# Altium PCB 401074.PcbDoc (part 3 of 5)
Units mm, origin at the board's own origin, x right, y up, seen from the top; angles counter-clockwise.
Board outline 70.15 x 35.15 mm, 6 copper layers (Top Layer, Mid-Layer1, Mid-Layer2, Mid-Layer3, Mid-Layer4, Bottom Layer), stack 1.549 mm thick; 239 components, 182 nets, 1034 pads, 1263 vias.
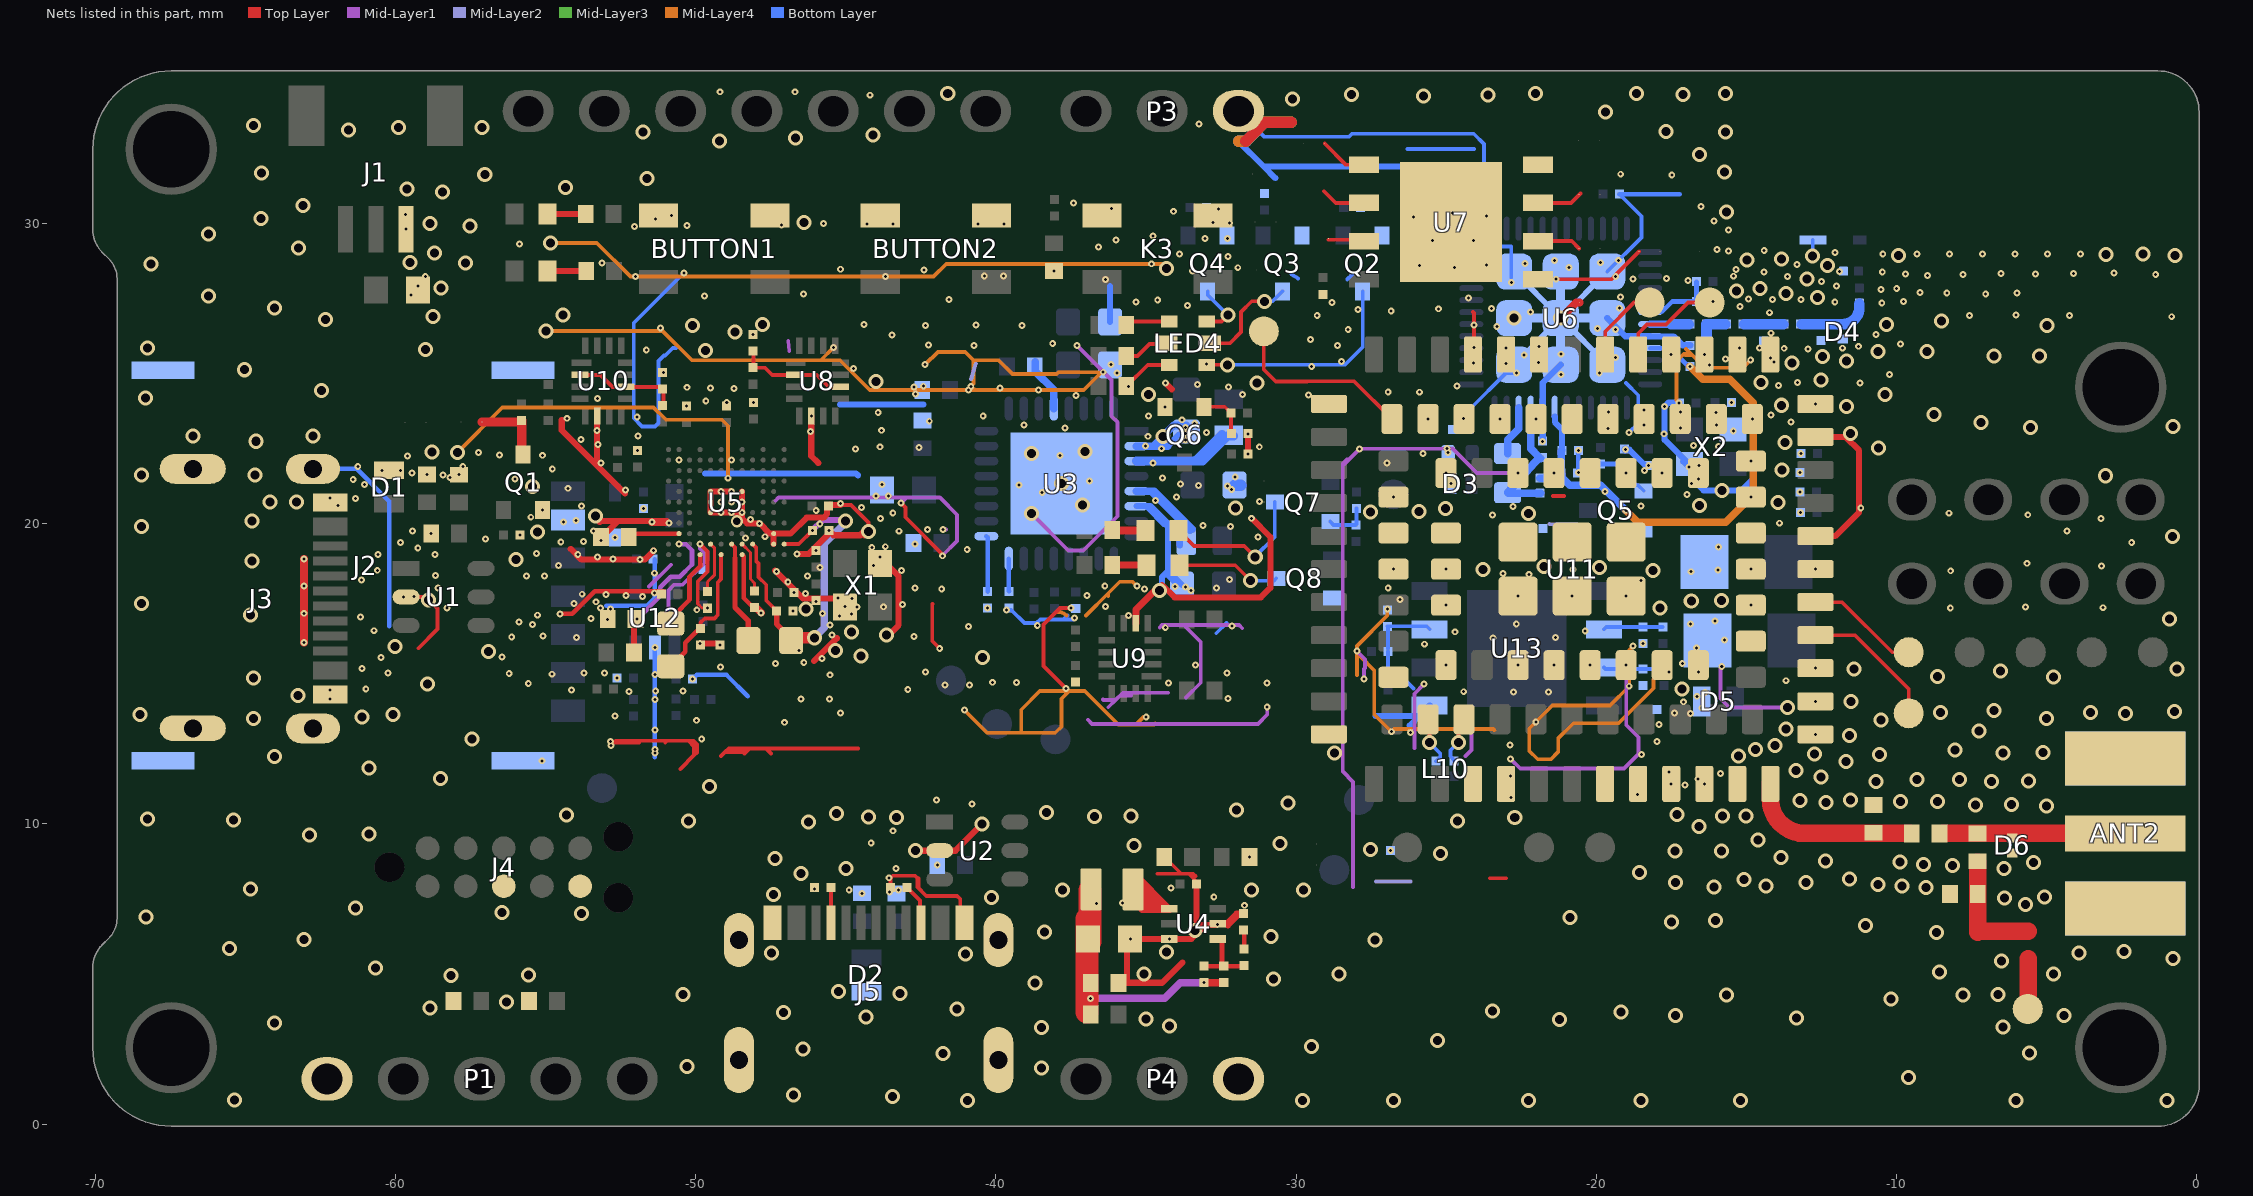
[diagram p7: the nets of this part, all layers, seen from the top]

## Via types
v1: diameter 0.23, hole 0.1, Top Layer to Mid-Layer1, tented both sides, 505 vias
v2: diameter 0.5, hole 0.3, Top Layer to Bottom Layer, tented both sides, 430 vias
v3: diameter 0.23, hole 0.1, Mid-Layer4 to Bottom Layer, tented both sides, 176 vias
v4: diameter 0.23/0.23 (per signal layer), hole 0.1, Mid-Layer4 to Bottom Layer, tented both sides, 144 vias
v5: diameter 0.5, hole 0.3, Top Layer to Bottom Layer, tented top, 7 vias
v6: diameter 0.4, hole 0.25, Top Layer to Bottom Layer, tented both sides, 1 vias

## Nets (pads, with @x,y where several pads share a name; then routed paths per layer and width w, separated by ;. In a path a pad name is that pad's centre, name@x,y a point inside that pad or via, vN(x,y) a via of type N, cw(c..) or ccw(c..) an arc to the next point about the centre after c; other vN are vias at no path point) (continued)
GND: ANT1.2 ANT2.2 BUTTON1.3 BUTTON1.4 BUTTON2.3 BUTTON2.4 C1.1 C2.1 C3.1 C4.1 C5.1 C6.1 C7.1 C8.1 C9.1 C10.1 C11.1 C12.1 C13.1 C14.1 C15.1 C16.1 C17.1 C18.1 C20.1 C21.1 C22.1 C23.1 C24.1 C25.1 C26.1 C27.1 C28.1 C29.1 C30.1 C31.1 C32.1 C33.1 C34.1 C35.1 C36.1 C37.1 C38.1 C39.2 C40.1 C41.1 C42.1 C43.1 C44.1 C45.1 C47.1 C48.1 C49.1 C50.1 C51.1 C52.1 C53.1 C54.1 C55.1 C56.2 C57.1 C58.1 C59.1 C60.1 C61.1 C62.1 C63.1 C64.1 C65.1 C67.1 C68.2 C69.1 C70.1 C71.1 C72.1 C73.1 C74.1 C75.1 C76.1 C77.1 C78.1 C79.2 C80.2 D1.A D2.A D3.A D4.A D5.A D6.A D7.K J1.1 J2.0@-55.742,12.097 J2.0@-55.742,25.097 J2.0@-67.742,12.097 J2.0@-67.742,25.097 J2.5 J3.0 J3.A1 J3.A12 J3.B1 J3.B12 J4.3 J4.5 J5.0 J5.A1 J5.A12 J5.B1 J5.B12 K3.3 K3.4 P1.1 P3.3 P4.3 pad.10 Q1.S Q2.S Q3.S Q4.S Q5.E Q6.E Q7.S Q8.S R1.1 R4.1 R5.1 R10.1 R13.1 R20.1 R22.2 R27.2 R28.2 R29.2 R31.2 R32.2 R33.1 R34.1 R45.2 R46.2 R53.2 R54.2 SB1.1 SB5.1 SB16.1 U1.2 U2.2 U3.0 U3.2 U3.6 U4.2 U4.6 U5.A5 U5.B2 U5.B9 U5.C2 U5.D12 U5.E5 U5.E6 U5.E7 U5.E8 U5.F5 U5.F6 U5.F7 U5.F8 U5.G5 U5.G6 U5.G7 U5.G8 U5.K6 U5.K11 U6.32 U6.44 U6.49 U7.4 U7.9 U8.6 U9.6 U10.6 U11.1 U11.2 U11.3 U11.4 U11.8 U11.9 U11.10 U11.26 U11.27 U11.30 U11.31 U11.32 U11.33 U11.34 U11.36 U11.37 U11.40 U11.41 U11.44 U11.45 U11.46 U11.47 U11.48 U11.49 U11.50 U11.51 U11.52 U11.53 U11.54 U11.55 U11.56 U11.68 U11.69 U11.70 U11.71 U11.72 U11.73 U11.74 U11.75 U11.76 U11.77 U11.78 U11.80 U11.81 U11.83 U11.84 U11.85 U11.86 U11.87 U11.88 U11.89 U11.90 U11.91 U11.92 U11.93 U11.94 U11.95 U11.96 U11.97 U11.98 U11.99 U11.102 U11.106 U11.107 U11.108 U11.109 U12.2 U13.1 X1.2 X1.4 X2.2 X2.4 | length 393.3
  Top Layer w0.102: -49.929,18.072 -49.929,17.324 -49.79,17.184 v1(-49.61,17.184)
  Top Layer w0.127: v1(-59.731,17.554) -59.553,17.554 -59.552,17.556 -58.991,17.556 -58.599,17.164 -58.599,16.481 -59.234,15.846 ; v1(-52.82,12.604) -52.729,12.696 ; -51.88,12.696 -52.729,12.696 ; -51.013,12.696 -50.947,12.762 ; -50.509,11.827 -50.052,12.284 ; -49.929,18.072 -49.609,18.392 -49.609,19.071 v1(-49.85,19.312) ; -49.15,12.251 -49.017,12.385 ; -48.369,12.34 -48.324,12.385 ; -47.491,12.34 -47.659,12.508 ; C29.1@-45.572,20.575 -45.524,20.624 C29.1@-45.505,20.624 ; -45.178,20.611 -44.82,20.611 -44.244,20.035 v2(-44.244,19.729) ; -44.597,12.508 -47.659,12.508 ; R34.1@-43.507,7.875 -43.507,8.192 -43.433,8.267 -42.689,8.267 -42.615,8.192 -42.615,7.891 -42.321,7.597 -41.296,7.597 -41.188,7.489 ; v1(-43.155,20.679) -43.014,20.538 -43.014,20.207 v1@-41.758,18.951 ; -42.574,7.883 -42.574,8.184 ; v1@-42.301,19.794 v1(-42.273,19.794) ; -42.108,17.321 -42.117,17.312 -42.117,16.082 v1(-41.87,15.835) ; J5.B1@-41.188,6.704 -41.188,7.488 ; v1(-37.663,14.504) -38.418,15.259 -38.418,16.635 -37.868,17.184 v1(-37.495,17.184) ; -34.626,8.333 -33.825,8.333 ; C17.1@-34.392,8.899 -33.825,8.333 ; -33.348,8.254 -33.426,8.333 -33.572,8.333 ; R10.1@-33.341,8.102 -33.572,8.333 ; U11.95@-28.907,23.979 U11.95@-28.849,23.979 ; -24.107,27.039 -24.079,27.012 v1(-24.079,26.613) v1(-24.079,25.86) ; -23.549,8.182 -23.007,8.182 ; -21.442,20.912 -21.074,20.912 ; -52.729,12.696 -52.663,12.762 -50.947,12.762 ; -50.947,12.762 -50.242,12.762 ; -50.242,12.762 -50.074,12.762 -49.958,12.647 -49.958,12.377 -50.052,12.284 ; -50.242,12.762 -50.052,12.572 -50.052,12.284 ; -49.017,12.385 -48.894,12.508 -48.201,12.508 ; -49.017,12.385 -48.324,12.385 ; -48.324,12.385 -48.201,12.508 ; -48.201,12.508 -47.659,12.508 ; -33.825,8.333 -33.572,8.333
  Top Layer w0.152: v1(-54.511,16.99) -54.11,16.99 -53.358,17.742 C31.1@-51.067,17.742 ; U5.A5@-48.45,18.962 -48.398,18.91 -48.398,17.52 -48.082,17.204 C35.1@-48.045,17.204 ; C35.1@-48.045,17.134 C35.1@-48.014,17.134
  Top Layer w0.203: -54.457,23.446 -54.457,23.105 -53.279,21.927 ; -54.16,19.152 -53.807,18.799 v1(-51.85,18.799) -51.694,18.799 v1(-51.4,19.092) ; U10.6@-53.279,23.581 v1(-53.279,23.104) -53.279,21.927 ; v2@-53.194,20.053 -53.165,20.082 -52.587,20.082 ; v1(-53.155,19.429) C34.1@-53.155,19.553 -53.116,19.553 -52.587,20.082 ; -52.347,20.995 -53.279,21.927 ; U5.D12@-50.9,20.012 -51.462,20.012 v1@-51.531,20.082 ; v1(-50.889,20.016) -50.956,20.082 v1@-51.531,20.082 ; v1(-49.85,16.004) -49.246,16.004 v1(-49.188,15.946) C25.1@-49.188,15.942 ; v1(-48.8,21.062) U5.G8@-49.5,21.062 U5.F8@-49.5,20.712 U5.E8@-49.5,20.362 v1(-48.8,20.362) v1(-48.45,20.362) ; U5.G5@-48.45,21.062 v1(-48.45,20.712) v1(-48.45,20.362) ; U5.B2@-47.4,19.312 U5.C2@-47.4,19.662 ; v1@-47.355,18.438 v1(-47.312,18.395) -46.424,17.508 X1.2@-45.098,17.508 ; v1@-46.611,18.989 -46.226,18.989 C27.1@-45.562,19.653 ; v1(-46.147,23.582) -46.147,22.248 -45.915,22.016 ; -46.052,15.423 -45.297,16.178 ; v1(-45.987,17.404) C79.2@-45.987,17.429 ; C29.1@-45.572,20.575 -45.621,20.527 -45.621,20.316 -45.74,20.197 -46.306,20.197 -46.84,19.662 U5.C2@-47.4,19.662 ; v1(-45.562,19.768) -45.404,19.61 -44.519,19.61 v2@-44.449,19.679 ; C29.1@-45.524,20.624 -45.524,20.611 -45.178,20.611 ; X1.2@-45.11,17.312 v1(-45.03,17.231) ; v2@-44.432,19.662 v2@-44.379,19.61 ; v1(-43.867,18.877) -43.238,18.248 -43.238,16.616 v2@-43.606,16.249 ; v2(-42.672,9.102) U2.2@-41.87,9.102 -41.351,9.102 v2(-40.459,9.994) ; C21.1@-35.917,4.703 -35.616,4.703 ; C20.1@-35.629,5.929 -35.629,4.716 -35.616,4.703 ; C20.1@-35.527,6.167 v1(-35.522,6.161) v1(-34.218,6.161) -33.487,6.161 -33.174,6.474 -33.174,6.622 ; v2@-34.461,17.95 -34.048,17.538 -31.179,17.538 -30.859,17.858 -30.859,19.55 v1(-31.483,20.174) ; v1(-34.356,24.683) -34.143,24.469 ; -33.783,5.384 -34.464,4.703 -35.616,4.703 ; R10.1@-33.314,7.955 -33.314,6.762 -33.174,6.622 ; -32.273,6.618 -31.923,6.968 ; R13.1@-31.75,7.011 -31.98,7.011 -32.33,6.661 U4.2@-32.618,6.661 -32.657,6.622 -33.174,6.622 ; v1(-31.608,22.307) v1(-31.608,22.989) R46.2@-31.6,22.996 ; U11.41@-12.707,19.579 -12.047,19.579 -11.252,20.374 -11.252,22.433 -11.698,22.879 U11.44@-12.707,22.879 ; -52.587,20.082 v1@-51.531,20.082 ; v1(-48.45,20.362) -48.45,20.166 -48.286,20.001 v1(-47.869,20.001) -47.53,19.662 U5.C2@-47.4,19.662
  Top Layer w0.229: U9.6@-35.338,16.677 -35.338,17.133 -34.697,17.773 v2(-34.544,17.773)
  Top Layer w0.254: v1(-63.043,16.03) v1(-63.043,17.01) v1(-63.043,17.917) v1(-63.043,18.824) ; C35.1@-48.045,17.204 -47.994,17.204 v1@-47.816,17.026 ; v5(-21.187,26.837) -20.665,27.36 SB1.1@-20.555,27.36
  Top Layer w0.381: -31.672,32.735 -31.037,33.369 -30.156,33.369
  Mid-Layer1 w0.127: -51.551,17.898 -50.825,18.624 ; -50.903,17.129 -50.903,17.773 -50.717,17.959 -50.435,17.959 -49.709,18.686 ; v1@-49.86,19.312 v1@-49.85,19.302 ; v1(-49.85,19.312) v1@-49.85,19.302 ; -47.346,20.754 -47.234,20.867 -42.968,20.867 ; -46.914,26.08 -46.883,25.735 ; v1(-43.155,20.679) -42.968,20.867 ; v1(-41.783,18.925) -41.29,19.419 -41.29,20.29 -41.866,20.867 -42.968,20.867 ; v1(-41.758,19.798) v1@-41.651,19.798 ; v5(-38.818,20.328) -37.59,19.1 -37.089,19.1 -35.947,20.242 -35.947,23.375 -36.146,23.574 -36.146,24.778 v1(-37.3,25.932) ; -36.929,13.462 -36.793,13.326 -31.272,13.326 -30.962,13.636 v1(-30.962,13.886) ; -36.427,14.137 -36.412,14.122 -36.015,14.122 ; -36.255,13.882 -36.015,14.122 ; -35.835,14.276 -35.496,14.276 ; -34.542,16.539 -34.464,16.618 -31.903,16.618 -31.795,16.509 ; -34.271,14.362 -35.775,14.362 -36.015,14.122 ; -33.679,16.559 -33.179,16.058 -33.179,14.694 -33.666,14.207 ; -28.265,22.1 -28.444,21.921 ; -28.101,7.89 -28.101,11.393 -28.444,11.736 -28.444,21.921 ; v1(-27.979,15.748) -27.709,15.478 -27.709,15.179 -27.739,15.15 v1(-27.739,14.823) ; -26.061,12.524 -26.061,14.328 v1(-25.739,14.65) ; -24.359,12.251 -24.155,12.455 -24.155,12.999 -24.206,13.05 ; v1(-22.858,12.161) -22.533,11.836 -19.075,11.836 -18.593,12.318 -18.593,12.879 -19.007,13.293 v1(-19.007,15.279) ; v1(-22.607,21.679) -23.973,21.679 -24.793,22.499 v1(-24.972,22.499) -24.979,22.492 -27.882,22.492 v1(-27.889,22.485) -28.238,22.136 -28.302,22.136 -28.444,21.994 -28.444,21.921 ; v1(-15.825,15.242) -15.867,15.199 -15.867,14.168 -15.572,13.873 v2(-13.637,13.873) ; v1@-49.85,19.302 -49.85,19.166 -49.709,19.025 -49.709,18.686 ; v1@-49.85,19.302 -49.597,19.049 -49.597,18.798 -49.709,18.686
  Mid-Layer3 w0.381: -31.672,32.735 -31.037,33.369 -30.156,33.369
  Mid-Layer4 w0.127: v2(-57.935,22.37) -56.441,23.864 -51.398,23.864 -50.988,23.454 -49.119,23.454 -48.92,23.255 v3(-48.92,21.508) ; v2(-54.987,26.414) -51.102,26.414 -50.125,25.437 -45.831,25.437 ; v2(-54.827,29.347) -53.291,29.347 -52.17,28.225 v3(-52.003,28.225) v3(-43.673,28.225) -42.077,28.225 -41.655,28.646 -34.463,28.646 v2(-34.31,28.493) ; v2@-48.681,26.336 v2(-48.681,26.378) ; v4(-45.408,25.86) -45.831,25.437 ; v4(-42.355,25.29) -41.932,25.713 -41.019,25.713 -40.74,25.435 ; v3(-41.051,13.787) -40.292,13.028 -39.157,13.028 ; -37.931,17.053 cw(c-37.931,16.652) -37.648,16.935 ; -36.995,16.938 -36.259,17.674 ; v4@-36.442,25.074 v4@-36.478,25.038 ; v4(-36.424,25.038) v4@-36.478,25.038 ; -36.259,17.575 -36.259,17.674 ; v3(-35.306,17.916) -35.448,18.058 -35.875,18.058 -36.259,17.674 ; v3(-34.993,13.552) -35.079,13.552 -35.33,13.301 ; -34.692,13.347 -34.738,13.301 -35.33,13.301 ; -27.975,14.943 -27.975,15.921 -26.963,16.934 v4(-26.963,17.151) ; -27.859,15.565 -27.399,15.106 -27.399,13.642 v3(-26.823,13.065) -26.737,13.151 -23.43,13.151 -23.39,13.111 ; v4(-18.775,15.92) -18.905,15.789 v4(-18.905,14.58) -19.549,13.937 -21.471,13.937 v4(-22.019,13.389) -22.235,13.173 -22.235,12.427 -21.955,12.147 -21.511,12.147 -21.273,12.385 -21.273,12.839 -20.765,13.347 -19.26,13.347 -18.096,14.511 -18.096,14.8 -17.899,14.997 ; v3(-17.251,24.021) -17.335,24.105 -17.335,25.398 -17.076,25.656 -16.858,25.656 ; -17.038,25.605 -16.82,25.605 ; -17.012,25.811 -16.858,25.656 ; -16.52,25.337 v4@-16.302,25.337 ; v4(-16.231,25.284) -16.485,25.284 ; v4(-14.859,25.445) -15.116,25.188 -16.389,25.188 -16.485,25.284 ; -45.831,25.437 -45.196,25.437 -44.203,24.444 -40.697,24.444 ; -40.74,25.435 -39.908,25.435 -39.448,24.975 -37.982,24.975 -37.918,25.038 v4@-36.478,25.038 ; -40.74,25.435 -40.74,24.652 v4(-40.836,24.556) -40.809,24.556 -40.697,24.444 ; -40.697,24.444 -37.073,24.444 v4@-36.478,25.038 ; -39.157,13.028 -38.022,13.028 -37.818,13.232 -37.818,14.161 -37.562,14.417 ; -39.157,13.028 -39.157,13.798 -38.538,14.417 -37.562,14.417 ; -37.562,14.417 -37.039,14.417 -35.922,13.301 -35.33,13.301 ; -16.858,25.656 -16.485,25.284
  Mid-Layer4 w0.381: -31.92,32.735 -31.672,32.735 -31.037,33.369 -30.156,33.369
  Mid-Layer2 w0.127: -40.83,24.801 -40.665,25.318 ; -27.342,8.073 -26.192,8.073 ; -21.561,19.984 -21.55,19.974 -20.65,19.974
  Mid-Layer2 w0.152: -17.944,21.304 -17.608,21.304
  Bottom Layer w0.127: -50.658,25.849 -50.759,25.849 -51.012,25.596 -51.053,25.596 -51.235,25.415 -51.235,23.353 -51.354,23.233 -51.781,23.233 -52.061,23.513 -52.061,26.673 v3(-50.394,28.341) ; v3(-39.649,17.12) -39.487,17.12 -39.05,16.682 -38.647,16.682 -38.521,16.808 -37.432,16.808 v3(-37.385,16.854) ; -37.745,16.809 -37.619,16.935 ; -32.661,16.343 -32.322,16.682 ; P3.3@-31.92,33.735 -31.287,33.102 -31.068,32.883 -28.231,32.883 -28.134,32.98 -24.085,32.98 -23.745,32.64 -23.745,29.416 -23.556,29.227 ; -30.161,28.301 -29.938,28.164 ; Q7.S@-28.862,20.062 -28.751,19.952 R54.2@-28.012,19.952 -27.985,19.979 R53.2@-27.985,20.502 ; -28.3,28.129 -28.132,28.297 ; -26.417,14.905 -26.417,14.832 -26.088,14.502 ; -26.299,32.475 -24.074,32.475 ; -24.458,23.805 -24.22,23.805 -23.013,25.011 v4(-22.657,25.011) ; -23.369,29.04 -23.556,29.227 ; U6.49@-22.835,28.185 -22.835,29.227 -23.556,29.227 ; U6.49@-19.637,28.387 -18.502,29.522 -18.502,30.235 C41.1@-19.236,30.969 ; -19.013,24.678 -18.608,24.273 -18.608,23.33 v4(-18.908,23.029) ; v2@-12.802,28.949 v2@-12.802,28.92 ; v2(-12.799,28.917) v2@-12.802,28.92 ; ANT1.2@-12.791,29.444 -12.791,28.931 v2@-12.802,28.92
  Bottom Layer w0.152: J3.0@-62.747,21.82 -61.286,21.82 -60.199,20.732 -60.199,16.575 ; -52.975,17.264 -51.615,17.264 -51.368,17.511 C71.1@-51.368,18.805 ; -51.368,12.216 -51.359,12.225 v3(-51.359,14.97) v3(-51.359,15.867) ; v3(-50.1,14.823) -49.967,14.956 -48.971,14.956 -48.26,14.245 ; C51.1@-20.625,21.676 v3(-20.6,21.701) -20.6,21.702 v3(-20.6,22.439) ; C41.1@-19.236,30.969 -17.217,30.969 ; R45.2@-19.055,22.486 R45.2@-19.034,22.464
  Bottom Layer w0.203: -49.68,21.662 -44.654,21.662 -44.597,21.606 ; -45.191,23.961 -42.418,23.961 ; C14.1@-36.194,26.714 -36.194,27.911 ; U3.6@-35.318,20.578 -34.848,20.578 -34.271,20.001 -34.271,18.41 ; U3.6@-34.948,20.54 -34.371,19.963 ; v2@-34.461,17.95 -34.461,18.219 -34.271,18.41 ; -34.274,22.578 -33.886,22.966 C12.1@-33.613,22.966 ; C13.1@-34.025,18.042 -34.271,18.288 -34.271,18.41 ; C13.1@-33.805,17.952 -34.267,18.414 -34.271,18.41 ; -31.92,32.735 -31.075,31.89 ; -30.69,31.504 -31.075,31.89 ; -27.36,13.589 -25.898,13.589 ; -26.221,13.267 -25.898,13.589 ; C40.1@-25.946,28.574 -25.946,31.433 -26.402,31.89 -31.075,31.89 ; U13.1@-25.551,13.937 -25.898,13.589 ; C45.1@-21.787,22.753 U6.44@-21.787,23.857 -21.787,24.687 U6.49@-21.187,25.287 ; U6.49@-19.637,26.837 -19.037,26.237 ; -18.905,22.459 C42.1@-18.363,21.917 ; C39.2@-17.226,24.021 v3(-17.251,24.021) -17.6,24.021 v4(-17.73,23.892) -17.73,22.785 X2.2@-16.911,21.966 ; X2.2@-17.051,22.07 -17.109,22.07 v3(-16.914,21.875) -16.718,21.68 -16.718,21.392 -16.426,21.1 v2(-15.822,21.1) -15.154,21.1 -14.771,21.483 -14.771,24.019 -15.551,24.799 ; C49.1@-16.865,25.935 C49.1@-16.885,25.935 -17.129,25.935 -17.425,26.231 U6.32@-18.2,26.231 ; -19.037,26.237 U6.32@-18.207,26.237 U6.32@-18.2,26.231 ; -19.037,26.237 -19.03,26.231 U6.32@-18.2,26.231
  Bottom Layer w0.254: U3.2@-35.318,22.578 -34.274,22.578 ; -34.731,22.604 -34.07,23.265 C12.1@-33.654,23.265
  Bottom Layer w0.381: C9.1@-32.049,21.278 C9.1@-31.84,21.278 ; -31.92,32.735 -31.655,32.735 -31.287,33.102
  other v1: -32.614,6.649 -31.716,7.284 -43.54,7.733 -44.884,7.797 -46.038,7.834 -43.557,8.2 -43.322,8.511 -31.549,8.899 -44.151,9.355 -43.433,9.766 -40.798,10.657 -41.982,10.795 -22.841,10.866 -18.636,10.97 -17.507,11.329 -16.407,11.329 -22.864,11.591 -51.358,12.471 -22.88,12.618 -12.707,12.979 -12.707,14.079 -62.172,14.15 -46.488,14.152 -45.537,14.152 -52.222,14.402 -24.418,14.397 -22.767,14.386 -21.59,14.386 -51.328,14.419 -50.424,14.415 -62.172,14.45 -54.134,14.45 -60.986,14.482 -42.934,14.47 -41.688,14.627 -40.878,14.614 -55.573,14.675 -40.118,14.712 -39.307,14.699 -13.688,14.764 -45.525,14.962 -54.789,14.98 -60.249,15.018 -56.208,15 -53.715,15.018 -53.038,15.024 -42.346,15.058 -17.574,15.049 -61.107,15.173 -12.707,15.179 -49.169,15.224 -25.007,15.279 -22.607,15.279 -21.407,15.279 -20.207,15.279 -47.346,15.339 -17.139,15.335 -46.397,15.374 -60.472,15.539 -25.723,15.979 -23.449,16.182 -53.967,16.204 -21.361,16.204 -55.089,16.251 -45.458,16.291 -24.715,16.393 -60.706,16.428 -20.371,16.418 -34.358,16.528 -45.525,16.625 -22.668,16.647 -55.887,16.713 -52.928,16.797 -53.48,16.833 -61.165,16.886 -45.215,16.915 -55.27,16.945 -44.801,16.989 -47.816,17.025 -46.754,17.093 -49.962,17.126 -52.832,17.147 -58.286,17.185 -8.214,17.185 -3.129,17.195 -5.713,17.216 -25.007,17.279 -14.857,17.279 -54.057,17.333 -53.321,17.393 -58.891,17.46 -44.794,17.5 -45.25,17.519 -59.374,17.561 -51.765,17.571 -22.607,17.579 -20.807,17.579 -19.007,17.579 -52.325,17.599 -36.965,17.599 -53.776,17.644 -52.979,17.64 -46.727,17.699 -33.499,17.773 -41.803,17.815 -35.052,17.825 -58.583,17.851 -32.648,17.853 -36.373,17.923 -46.931,18.055 -61.122,18.115 -32.223,18.137 -58.664,18.269 -55.626,18.25 -55.037,18.246 -60.603,18.443 -8.199,18.425 -26.757,18.479 -25.007,18.479 -14.857,18.479 -12.707,18.479 -3.175,18.581 -54.564,18.602 -44.071,18.609 -5.659,18.675 -52.752,18.817 -53.269,18.882 -60.585,18.962 -58.678,18.968 -53.924,18.968 -55.296,19.002 -46.618,18.989 -45.987,19.108 -59.254,19.189 -44.133,19.194 -43.683,19.226 -59.822,19.373 -54.491,19.383 -2.17,19.372 -53.732,19.394 -56.998,19.485 -47.687,19.559 -31.264,19.553 -55.849,19.618 -58.807,19.659 -59.425,19.745 -53.405,19.75 -4.326,19.75 -32.188,19.903 -33.096,19.927 -54.402,20.053 -51.459,20.049 -3.192,20.162 -55.49,20.208 -23.464,20.282 -5.632,20.291 -8.253,20.343 -49.15,20.362 -55.099,20.449 -11.195,20.519 -22.776,20.568 -61.907,20.605 -53.807,20.584 -18.514,20.584 -49.15,20.712 -48.8,20.712 -31.217,20.734 -34.681,20.765 -62.172,20.85 -61.323,20.835 -26.757,20.879 -14.857,20.879 -33.991,20.887 -38.456,21.026 -49.15,21.062 -19.71,21.066 -52.34,21.117 -54.249,21.173 -33.246,21.262 -32.288,21.248 -39.232,21.282 -61.033,21.294 -33.853,21.313 -36.883,21.419 -61.403,21.471 -56.022,21.482 -16.599,21.475 -34.445,21.517 -58.414,21.617 -58.949,21.633 -57.877,21.625 -59.447,21.677 -25.007,21.679 -21.407,21.679 -19.007,21.679 -17.807,21.679 -60.452,21.762 -59.83,21.765 -54.774,21.82 -61.251,21.894 -16.579,21.934 -53.154,22.016 -34.771,22.016 -14.857,22.079 -50.55,22.112 -48.8,22.112 -59.6,22.243 -55.099,22.273 -37.867,22.264 -56.535,22.283 -57.226,22.369 -51.937,22.426 -44.678,22.485 -34.481,22.49 -42.565,22.535 -43.861,22.554 -31.227,22.554 -15.931,22.558 -16.772,22.594 -53.246,22.631 -33.687,22.779 -53.822,22.793 -34.938,22.905 -51.918,22.92 -32.979,23.032 -46.173,23.069 -43.811,23.105 -19.609,23.159 -37.704,23.181 -17.199,23.181 -33.68,23.201 -39.068,23.284 -18.421,23.276 -16.002,23.276 -13.522,23.374 -42.219,23.406 -25.607,23.479 -24.426,23.492 -23.207,23.479 -22.007,23.479 -14.807,23.479 -54.28,23.504 -51.944,23.54 -40.422,23.58 -34.918,23.583 -43.918,23.699 -16.022,23.699 -19.591,23.709 -17.196,23.709 -18.407,23.776 -34.372,23.887 -50.303,23.911 -13.922,23.969 -12.707,23.979 -48.963,24.029 -48.071,24.029 -49.662,24.075 -53.273,24.169 -37.338,24.263 -29.593,24.274 -42.677,24.313 -31.788,24.295 -26.932,24.376 -25.894,24.371 -40.909,24.445 -38.577,24.448 -49.5,24.513 -48.724,24.502 -39.857,24.513 -50.292,24.537 -32.256,24.546 -24.638,24.578 -33.289,24.627 -13.307,24.7 -51.074,25.027 -29.48,25.227 -23.007,25.328 -24.095,25.347 -21.92,25.365 -28.494,25.394 -14.207,25.51 -17.507,25.629 -16.407,25.629 -51.644,25.78 -23.015,25.847 -21.914,25.9 -40.724,25.922 -28.626,25.922 -42.239,25.943 -38.106,25.992 -29.516,26.131 -43.454,26.279 -48.087,26.296 -14.19,26.337 -28.265,26.462 -51.175,26.506 -23.317,26.556 -42.346,26.599 -39.125,26.599 -40.66,26.605 -44.392,26.629 -29.298,26.921 -14.236,27.019 -22.2,27.046 -26.833,27.083 -27.94,27.121 -25.259,27.151 -23.495,27.163 -15.215,27.223 -33.619,27.261 -28.8,27.36 -35.338,27.375 -34.609,27.437 -41.554,27.467 -24.257,27.508 -19.195,27.539 -49.708,27.582 -59.487,27.618 -46.407,27.645 -59.253,27.917 -16.947,28.088 -18.774,28.146 -17.664,28.161 -59.004,28.223 -38.066,28.411 -15.354,28.459 -24.731,28.527 -25.891,28.592 -23.654,28.603 -34.818,28.65 -32.263,28.889 -33.886,28.98 -36.576,29.202 -55.866,29.312 -36.003,29.445 -25.466,29.426 -24.092,29.421 -33.032,29.497 -32.279,29.497 -34.773,29.569 -59.653,29.805 -47.137,29.939 -43.428,29.967 -39.728,29.967 -45.74,29.996 -44.29,29.982 -40.59,29.982 -51.328,30.143 -26.094,30.206 -50.8,30.25 -23.654,30.245 -59.665,30.285 -24.793,30.348 -32.588,30.471 -36.146,30.488 -37.416,30.673 -33.229,33.299 -44.194,34.264 -49.188,34.379 -46.689,34.379
  other v2: -40.945,0.785 -29.787,0.785 -26.763,0.785 -22.257,0.785 -18.52,0.785 -15.196,0.785 -6.031,0.785 -0.991,0.785 -65.354,0.804 -43.444,0.915 -46.741,0.965 -9.598,1.541 -38.48,1.864 -50.282,1.915 -41.758,2.347 -5.575,2.362 -46.418,2.492 -29.484,2.578 -25.286,2.774 -38.48,3.208 -6.452,3.226 -34.222,3.258 -64.027,3.363 -21.231,3.48 -35.007,3.493 -13.337,3.533 -44.318,3.556 -17.368,3.607 -4.432,3.62 -47.066,3.708 -19.178,3.723 -23.458,3.757 -41.298,3.834 -58.848,3.867 -56.306,4.063 -10.193,4.171 -15.659,4.297 -7.792,4.297 -50.421,4.307 -6.627,4.314 -43.195,4.348 -45.237,4.42 -38.696,4.704 -30.759,4.826 -58.145,4.948 -55.573,4.956 -35.072,4.997 -28.575,4.997 -4.775,5 -8.575,5.055 -60.655,5.201 -6.513,5.436 -0.795,5.506 -41.011,5.654 -47.475,5.69 -3.92,5.69 -34.31,5.733 -2.433,5.741 -65.532,5.842 -63.043,6.141 -27.373,6.129 -30.841,6.248 -38.374,6.395 -8.672,6.385 -33.361,6.443 -11.038,6.616 -17.504,6.734 -16.035,6.776 -20.873,6.879 -68.301,6.893 -53.807,7.011 -56.443,7.047 -61.329,7.188 -5.713,7.316 -40.148,7.543 -6.41,7.535 -5.075,7.568 -47.404,7.64 -37.784,7.797 -31.484,7.797 -29.753,7.789 -64.821,7.834 -9.021,7.878 -16.075,7.896 -14.351,7.927 -9.822,7.928 -10.618,7.976 -17.368,8.046 -13.012,8.048 -15.081,8.141 -11.564,8.159 -46.488,8.344 -18.565,8.376 -44.992,8.502 -6.428,8.51 -8.136,8.611 -9.101,8.637 -5.444,8.713 -9.895,8.734 -12.362,8.756 -47.353,8.845 -13.856,8.877 -25.191,9.01 -17.379,9.093 -15.838,9.092 -27.519,9.144 -35.399,9.271 -30.543,9.335 -14.612,9.465 -62.853,9.631 -60.884,9.664 -16.585,9.906 -50.234,10.084 -46.234,10.066 -24.631,10.084 -65.39,10.119 -68.25,10.162 -43.315,10.211 -22.719,10.211 -44.245,10.23 -36.714,10.237 -35.504,10.259 -15.799,10.262 -15.025,10.262 -54.306,10.299 -17.323,10.311 -45.314,10.345 -38.322,10.379 -31.979,10.459 -5.012,10.586 -7.378,10.617 -6.172,10.643 -30.268,10.693 -12.352,10.707 -9.863,10.745 -8.644,10.745 -13.217,10.77 -11.54,10.789 -49.533,11.236 -10.688,11.405 -6.833,11.405 -5.613,11.43 -9.33,11.475 -7.899,11.475 -58.491,11.507 -12.52,11.556 -13.349,11.77 -60.885,11.852 -11.692,12.081 -64.027,12.242 -15.265,12.259 -12.733,12.32 -10.564,12.307 -28.73,12.35 -6.452,12.35 -5.126,12.369 -14.695,12.472 -8.052,12.462 -14.05,12.608 -57.442,12.82 -11.568,12.943 -7.256,13.095 -13.689,13.151 -10.517,13.453 -64.717,13.507 -5.012,13.507 -61.109,13.553 -68.5,13.646 -60.076,13.646 -2.37,13.666 -8.541,13.708 -3.539,13.708 -0.752,13.736 -6.751,13.779 -11.518,14.064 -63.246,14.266 -17.148,14.487 -58.928,14.65 -64.726,14.848 -4.775,14.885 -8.644,14.909 -6.545,15.091 -11.413,15.158 -0.662,15.161 -40.452,15.539 -44.485,15.58 -56.891,15.732 -45.334,15.773 -60.006,15.901 -43.637,16.285 -44.814,16.392 -0.913,16.82 -64.821,16.948 -46.323,17.147 -17.876,17.179 -68.453,17.339 -16.84,17.42 -15.836,17.428 -58.891,17.46 -18.106,18.44 -23.77,18.475 -19.891,18.541 -21.746,18.57 -64.77,18.748 -55.98,18.799 -0.811,19.57 -55.262,19.709 -68.453,19.896 -64.77,20.082 -53.337,20.242 -22.257,20.334 -27.523,20.382 -25.913,20.402 -25.026,20.502 -32.024,20.521 -16.561,20.607 -13.958,20.694 -64.175,20.715 -63.286,20.71 -55.426,21.231 -3.048,21.59 -68.453,21.62 -64.683,21.621 -13.813,21.779 -58.775,22.389 -10.61,22.51 -13.716,22.696 -64.643,22.739 -34.433,22.891 -66.747,22.92 -62.747,22.92 -11.54,23.004 -5.537,23.197 -0.79,23.23 -7.186,23.356 -8.761,23.637 -11.668,23.896 -13.829,23.938 -68.326,24.175 -34.915,24.295 -10.388,24.295 -62.456,24.429 -31.31,24.683 -14.523,24.697 -43.996,24.734 -12.525,24.78 -65.024,25.121 -13.482,25.348 -11.668,25.41 -12.469,25.569 -6.751,25.574 -5.238,25.578 -10.619,25.724 -8.982,25.724 -49.673,25.761 -58.992,25.788 -68.25,25.85 -50.1,26.588 -4.997,26.588 -10.331,26.622 -47.768,26.632 -8.499,26.749 -62.328,26.799 -58.742,26.901 -54.424,26.95 -64.027,27.171 -12.643,27.534 -66.218,27.575 -13.691,27.665 -15.33,27.736 -58.484,27.842 -14.553,27.833 -12.991,28.135 -12.295,28.592 -68.144,28.65 -57.664,28.683 -59.517,28.687 -14.984,28.779 -13.829,28.808 -9.946,28.924 -0.734,28.919 -3.023,28.956 -1.801,28.973 -58.689,29.016 -63.222,29.173 -66.218,29.642 -57.514,29.907 -58.84,29.984 -46.397,30.017 -64.472,30.154 -15.659,30.369 -63.081,30.597 -58.422,31.04 -59.616,31.139 -54.33,31.192 -51.616,31.485 -57.023,31.623 -64.463,31.668 -15.735,31.709 -16.558,32.294 -49.204,32.741 -46.676,32.84 -44.1,32.943 -51.759,33.044 -15.695,33.034 -17.684,33.058 -61.556,33.111 -59.899,33.19 -57.121,33.19 -64.717,33.258 -19.698,33.7 -30.121,34.137 -25.763,34.238 -23.61,34.264 -28.16,34.289 -17.109,34.289 -41.603,34.318 -22.031,34.318 -18.668,34.314 -15.705,34.318
  other v3: -36.65,7.35 -35.783,7.359 -44.458,7.681 -43.24,7.798 -41.951,8.632 -26.85,9.113 -55.118,12.097 -51.358,12.36 -52.832,12.745 -49.797,12.817 -26.19,13.033 -51.358,13.126 -47.038,13.38 -49.967,13.446 -52.69,13.589 -45.18,13.683 -51.358,14.142 -32.264,14.177 -34.254,14.69 -30.969,14.691 -52.611,14.858 -32.3,15.024 -16.599,15.047 -45.791,15.502 -56.45,15.559 -46.562,15.773 -16.671,15.861 -15.732,16.115 -56.124,16.22 -42.723,16.24 -40.911,16.567 -32.136,16.581 -38.621,16.6 -55.428,16.637 -16.87,16.648 -16.049,16.75 -35.585,16.938 -45.781,17.001 -53.171,17.19 -40.277,17.186 -44.631,17.218 -43.744,17.226 -36.347,17.241 -43.112,17.304 -26.539,17.47 -51.369,17.684 -46.337,17.667 -42.689,17.851 -26.933,17.857 -34.03,17.899 -33.68,17.889 -46.274,18.251 -51.374,18.343 -43.138,18.431 -45.859,18.541 -40.954,19.13 -42.689,19.322 -52.68,19.533 -48.339,19.514 -43.224,19.742 -45.865,19.989 -13.906,20.009 -53.986,20.101 -48.178,20.129 -43.84,20.167 -43.434,20.35 -13.208,20.37 -45.983,20.436 -51.74,20.495 -44.474,20.531 -45.178,20.671 -43.996,20.911 -43.583,20.911 -13.216,21.052 -43.791,21.292 -24.842,21.33 -58.179,21.53 -13.215,21.698 -57.754,21.894 -26.98,22.01 -25.777,22.324 -13.193,22.328 -24.938,22.359 -35.022,22.587 -21.798,22.725 -33.68,22.996 -15.44,23.075 -33.377,23.327 -33.805,23.454 -14.19,23.615 -35.578,24.561 -32.978,25.319 -16.116,27.393 -36.353,28.129 -40.386,28.247 -39.747,28.247 -33.449,28.409 -42.397,28.439 -45.18,28.468 -31.943,28.518 -53.111,28.671 -52.029,29.885 -50.292,29.931 -32.765,30.021 -32.223,30.009 -16.083,30.074 -16.52,30.555 -17.489,31.601 -19.19,31.632
  other v4: -32.742,7.557 -34.17,7.859 -17.042,11.291 -16.622,11.488 -15.863,11.668 -17.581,11.717 -18.497,12.307 -17.986,12.741 -17.912,13.301 -16.865,13.668 -17.401,13.683 -16.482,13.857 -17.102,14.062 -16.648,14.245 -16.383,14.376 -33.347,15.288 -18.453,16.004 -18.517,18.109 -22.25,18.308 -23.114,18.333 -16.851,18.394 -20.772,18.468 -15.944,18.452 -15.931,19.212 -16.981,20.96 -32.145,21.135 -16.832,21.326 -32.028,21.554 -18.4,21.759 -18.257,21.928 -19.033,22.465 -17.747,22.988 -15.492,24.023 -42.723,24.55 -42.418,24.571 -13.93,24.593 -11.219,24.678 -13.307,24.7 -21.184,24.968 -10.236,24.958 -35.971,25.012 -19.904,25.011 -44.748,25.163 -36.162,25.29 -14.081,25.385 -15.695,25.477 -19.362,25.532 -22.403,25.616 -21.184,25.637 -12.956,25.81 -13.744,25.835 -11.806,25.837 -15.227,25.847 -14.572,25.842 -11.274,25.903 -9.866,25.976 -10.693,26.301 -19.362,26.465 -19.962,26.49 -0.838,26.886 -7.573,26.931 -4.242,26.931 -6.024,26.95 -19.236,27.169 -10.496,27.338 -12.061,27.375 -9.77,27.393 -14.94,27.481 -14.137,27.467 -13.183,27.467 -7.032,27.637 -8.33,27.68 -5.994,27.68 -9.225,27.698 -10.517,27.795 -9.996,27.824 -11.997,27.903 -22.835,28.024 -12.496,28.059 -21.348,28.135 -19.356,28.225 -15.437,28.235 -13.638,28.232 -8.97,28.255 -7.792,28.298 -1.372,28.298 -9.701,28.315 -6.528,28.322 -5.371,28.315 -4.103,28.322 -2.758,28.342 -14.416,28.377 -10.479,28.377 -11.898,28.391 -20.917,28.532 -13.32,28.625 -22.383,28.658 -19.862,28.684 -21.399,28.76 -19.264,28.766 -10.462,28.973 -9.325,28.976 -8.236,28.976 -7.147,28.976 -6.058,28.976 -4.969,28.976 -3.88,28.976 -12.057,29.026 -15.593,29.07 -14.411,29.09 -15.977,29.121 -15.598,29.78 -34.084,30.398
  other v5: -37.109,20.619 -37.818,21.328 -38.818,22.328 -37.033,22.397 -22.737,26.837
  other v6: -48.622,20.075
NetANT2_1: ANT2.1 C66.2 D6.K R37.2 | length 5.9
  Top Layer w0.584: R37.2@-8.434,9.676 C66.2@-7.301,9.676 ANT2.1@-2.505,9.676
NetC19_1: C19.1 R11.1 R12.2 U4.1 | length 2.4
  Top Layer w0.152: R11.1@-33.076,5.258 C19.1@-32.468,5.258 ; U4.1@-32.618,6.161 -32.468,6.161 C19.1@-32.468,5.258 ; R12.2@-31.732,5.281 -31.755,5.258 C19.1@-32.41,5.258 C19.1@-32.468,5.258
NetC19_2: C19.2 C20.2 C21.2 L3.2 R9.1 R11.2 | length 9.5
  Top Layer w0.254: v1(-33.076,4.708) C19.2@-32.41,4.708
  Top Layer w0.762: R9.1@-36.965,3.72 -36.965,6.838 ; C20.2@-36.863,6.076 L3.2@-36.863,7.784
  Mid-Layer1 w0.254: v1@-36.843,4.191 -34.38,4.191 -33.863,4.708 v1(-33.076,4.708)
  other v1: -36.843,4.184
NetC26_2: C26.2 C27.2 L4.1 U5.B1 U5.B4 | length 11.3
  Top Layer w0.127: U5.B4@-48.1,19.312 -47.984,19.196 -47.984,18.748 -47.901,18.665 -47.901,18.212 -47.647,17.958 -47.647,17.436 C26.2@-47.304,17.093 ; U5.B1@-47.05,19.312 -46.567,19.312 v1(-46.112,19.768)
  Top Layer w0.178: C26.2@-47.304,17.093 -47.304,16.655 L4.1@-46.818,16.169 ; L4.1@-46.818,16.219 L4.1@-46.818,16.169 ; L4.1@-46.614,16.348 -46.639,16.348 L4.1@-46.818,16.169
  Top Layer w0.381: L4.1@-46.573,16.194 v2(-46.048,16.194)
  Mid-Layer1 w0.203: v1(-46.112,19.768) -45.769,20.111 -45.705,20.111 -45.023,20.111 v2(-45.001,20.088)
  Mid-Layer2 w0.254: v2(-46.048,16.194) -45.715,16.527 -45.715,19.328 v2@-44.931,20.111
NetC32_2: C32.2 L5.1 U5.A7 | length 4.7
  Top Layer w0.127: C32.2@-49.836,16.496 -49.836,16.509 -49.836,16.697 -49.697,16.837 -49.373,16.837 -49.261,16.948 -49.261,18.04 -49.15,18.151 U5.A7@-49.15,18.962
  Top Layer w0.152: L5.1@-50.828,15.242 L5.1@-50.7,15.37 ; L5.1@-50.7,15.367 L5.1@-50.7,15.37 ; C32.2@-49.844,16.509 -49.836,16.509 -49.823,16.509 C32.2@-49.836,16.496 -49.874,16.496 -50.34,16.03 -50.34,15.73 L5.1@-50.7,15.37 ; U5.A7@-49.15,18.962 U5.A7@-49.144,18.956
NetC33_2: C33.2 R15.1 U5.B11 | length 4.9
  Top Layer w0.152: v1(-50.55,19.312) U5.B11@-50.536,19.312
  Top Layer w0.203: R15.1@-52.053,15.7 -52.053,16.764 C33.2@-52.003,16.814
  Mid-Layer1 w0.152: v1(-51.944,16.814) -51.174,17.584 -51.174,17.88 -50.833,18.221 -50.533,18.221 -50.12,18.633 -50.12,19.112 -50.321,19.312 v1(-50.55,19.312)
NetC34_2: C34.2 U5.C11 | length 1.7
  Top Layer w0.152: C34.2@-52.23,19.553 -52.121,19.662 U5.C11@-50.55,19.662
NetC35_2: C35.2 U5.B5 | length 1.8
  Top Layer w0.102: U5.B5@-48.45,19.312 -48.175,19.037 -48.175,18.15 -48.045,18.02 C35.2@-48.045,17.754 ; C35.2@-48.064,17.734 C35.2@-48.014,17.684
NetC36_2: C36.2 U5.B8 | length 1.7
  Top Layer w0.102: C36.2@-49.602,17.727 -49.602,18.058 -49.368,18.292 -49.368,19.18 U5.B8@-49.5,19.312
NetC45_2: C45.2 FB1.2 L6.1 U6.45 | length 4.5
  Bottom Layer w0.254: L6.1@-22.956,21.045 L6.1@-22.956,21.026 C45.2@-21.897,22.203 ; L6.1@-22.939,21.01 FB1.2@-21.881,21.01 FB1.2@-21.853,21.01 ; U6.45@-22.187,23.857 -22.187,23.023 -22.191,23.018 -22.191,22.498 C45.2@-21.897,22.203 ; C45.2@-21.86,22.167 C45.2@-21.897,22.203
NetC46_1: C46.1 C48.2 D4.K L9.2 | length 2.3
  Bottom Layer w0.356: L9.2@-13.151,26.637 D4.K@-11.796,26.637 ccw(c-11.796,27.189) -11.244,27.189 C46.1@-11.244,27.308
NetC47_2: C47.2 L8.2 L9.1 | length 1.3
  Bottom Layer w0.356: L8.2@-15.073,26.637 L9.1@-13.778,26.637
NetC49_2: C49.2 L7.2 L8.1 | length 1.3
  Bottom Layer w0.356: C49.2@-16.335,25.968 L7.2@-16.335,26.637 L8.1@-15.708,26.637
NetC51_2: C51.2 C52.2 C53.2 FB1.1 U6.33 U6.43 | length 17.6
  Mid-Layer4 w0.254: v4(-19.02,20.44) -18.626,20.046 -15.687,20.046 -14.771,20.962 -14.771,24.019 -15.562,24.81 -16.46,24.81 v4(-16.885,25.235)
  Bottom Layer w0.152: U6.33@-18.207,25.837 -17.53,25.837 -17.002,25.309 -16.959,25.309 v4(-16.885,25.235)
  Bottom Layer w0.203: U6.43@-21.385,23.559 -21.385,23.556 -21.383,23.554 -21.383,23.379 -21.15,23.145 C52.2@-21.15,22.439
  Bottom Layer w0.254: FB1.1@-21.876,21.506 -21.175,21.506 C51.2@-21.175,21.676 ; C52.2@-21.15,22.439 -21.175,22.413 C51.2@-21.175,21.676 ; v4(-19.02,20.44) -19.852,21.272 -20.881,21.272 -21.152,21.544 -21.152,21.653 C51.2@-21.175,21.676
NetC54_2: C54.2 R23.1 U6.30 | length 2.3
  Bottom Layer w0.152: U6.30@-18.207,27.037 -18.198,27.046 -17.817,27.046 -17.471,27.393 C54.2@-16.666,27.393 R23.1@-16.666,28.053
NetC65_2: C65.2 R37.1 U11.35 | length 5.8
  Top Layer w0.584: U11.35@-14.207,11.329 -14.207,10.827 ccw(c-13.056,10.827) -13.056,9.676 R37.1@-9.586,9.676
NetC66_1: C66.1 C80.1 SB4.2 SB5.2 | length 4
  Top Layer w0.584: SB5.2@-7.301,6.386 C66.1@-7.301,8.714 ; -7.301,6.426 -5.613,6.426
NetC75_2: C75.2 R49.1 R51.2 U13.3 | length 3
  Bottom Layer w0.127: R51.2@-26.942,14.997 -26.938,15.001 R49.1@-26.938,15.74 ; R49.1@-26.938,15.83 -26.938,16.552 C75.2@-26.963,16.576 -25.65,16.576 U13.3@-25.551,16.477
NetC77_2: C77.2 R50.1 U13.7 | length 2
  Bottom Layer w0.127: U13.7@-19.751,15.207 -19.698,15.154 R50.1@-17.749,15.154
NetC78_2: C78.2 R52.1 U13.6 | length 2
  Bottom Layer w0.127: U13.6@-19.751,16.477 -19.673,16.554 R52.1@-17.789,16.554
NetJ5_A5: J5.A5 R33.2 | length 1.2
  Top Layer w0.127: J5.A5@-45.488,6.704 -45.488,7.835 R33.2@-45.47,7.853
NetJ5_B5: J5.B5 R34.2 | length 1.4
  Top Layer w0.127: R34.2@-42.955,7.873 -42.525,7.442 -42.525,6.74 J5.B5@-42.488,6.704
NetL1_1: L1.1 U3.3 | length 4.8
  Bottom Layer w0.305: U3.3@-35.318,22.078 -33.123,22.078 -32.288,22.913 L1.1@-32.089,22.913 ; -33.308,22.122 L1.1@-32.473,22.957
NetL2_1: L2.1 U3.5 | length 5.2
  Bottom Layer w0.203: L2.1@-33.875,19.261 -33.875,20.077
  Bottom Layer w0.254: U3.5@-35.318,21.078 -34.969,21.078 -34.728,21.078 L2.1@-33.462,19.812 ; -34.805,21.054 L2.1@-33.533,19.783 ; L2.1@-33.698,19.807 L2.1@-33.527,19.807
NetL3_1: L3.1 U4.4 | length 5.1
  Top Layer w0.254: L3.1@-35.43,7.817 -35.43,7.467 -35.207,7.244 -35.182,7.244 L3.1@-35.13,7.192 ; L3.1@-35.398,7.82 -34.753,7.175 ; L3.1@-35.38,8.296 U4.4@-34.259,7.175 ; L3.1@-35.13,7.161 U4.4@-34.218,7.161 ; L3.1@-35.13,7.817 U4.4@-34.485,7.171
NetL4_2: L4.2 U5.B6 | length 3.4
  Top Layer w0.127: U5.B6@-48.8,19.312 -48.69,19.202 -48.69,18.848
  Top Layer w0.178: -48.69,18.848 -48.69,17.207 -48.242,16.759 L4.2@-48.242,16.169
NetL5_2: L5.2 U5.A9 | length 3
  Top Layer w0.152: L5.2@-50.828,16.665 -50.828,16.829 L5.2@-50.775,16.882 ; L5.2@-50.828,16.882 L5.2@-50.775,16.882 ; L5.2@-50.597,16.612 L5.2@-50.559,16.649 ; U5.A9@-49.85,18.962 -49.85,18.583 -50.204,18.23 -50.204,17.457 -50.236,17.425 -50.236,17.421 -50.649,17.008 -50.649,16.98 -50.551,16.882 L5.2@-50.775,16.882
NetL6_2: L6.2 U6.46 | length 1.7
  Bottom Layer w0.254: L6.2@-22.956,22.326 -22.956,22.793 -22.587,23.162 U6.46@-22.587,23.857
NetL7_1: L7.1 U6.31 | length 1.3
  Bottom Layer w0.254: U6.31@-18.207,26.637 -17.502,26.637
  Bottom Layer w0.356: -17.502,26.637 L7.1@-16.92,26.637
NetL10_1: L10.1 U11.59 | length 1.6
  Top Layer w0.127: U11.59@-25.607,13.479 -25.561,13.434 v2(-25.561,12.71)
  Bottom Layer w0.127: v2(-25.561,12.71) -25.561,12.703 -25.2,12.341 -25.2,12.219 L10.1@-25.337,12.082
NetL10_4: L10.4 U11.60 | length 1.6
  Top Layer w0.127: v2(-24.596,12.71) -24.596,13.29 U11.60@-24.407,13.479
  Bottom Layer w0.127: L10.4@-24.737,12.082 -24.737,12.126 -24.856,12.246 -24.856,12.45 v2(-24.596,12.71)
NetLED1_A: LED1.A R2.2 | length 1.3
  Top Layer w0.2: LED1.A@-54.934,30.3 R2.2@-53.661,30.3
NetLED2_A: LED2.A R3.2 | length 1.3
  Top Layer w0.2: LED2.A@-54.934,28.409 -54.927,28.402 R3.2@-53.642,28.402
NetLED4_A1: LED4.A1 R24.1 | length 1.7
  Top Layer w0.127: R24.1@-35.685,24.505 R24.1@-35.659,24.505 ; R24.1@-35.659,24.574 -35.647,24.574 -34.943,25.278 LED4.A1@-34.228,25.278
NetLED4_A2: LED4.A2 R25.1 | length 1.5
  Top Layer w0.127: R25.1@-35.659,25.574 -35.278,25.574 -34.879,25.974 -34.358,25.974 LED4.A2@-34.328,26.003
NetLED4_A3: LED4.A3 R26.1 | length 1.5
  Top Layer w0.127: R26.1@-35.659,26.613 -35.545,26.728 LED4.A3@-34.228,26.728
NetLED4_K1: LED4.K1 Q2.D | length 7.3
  Top Layer w0.127: LED4.K1@-32.978,25.278 -32.94,25.239 -32.893,25.286 v2(-32.278,25.286)
  Bottom Layer w0.127: v2(-32.278,25.286) -28.37,25.286 -27.783,25.872 Q2.D@-27.783,27.734
NetLED4_K2: LED4.K2 Q3.D | length 3.5
  Top Layer w0.127: LED4.K2@-32.878,26.003 -32.208,26.003 -31.833,26.378 -31.833,27.044 -31.476,27.401 v2(-31.056,27.401)
  Bottom Layer w0.127: v2(-31.056,27.401) -30.788,27.401 Q3.D@-30.455,27.734
NetLED4_K3: LED4.K3 Q4.D | length 1.9
  Top Layer w0.127: LED4.K3@-32.978,26.728 -32.49,26.728 v2(-32.275,26.944)
  Bottom Layer w0.127: Q4.D@-32.945,27.734 -32.945,27.613 v2(-32.275,26.944)
NetLED5_A: LED5.A R47.1 | length 1.1
  Top Layer w0.254: R47.1@-36.122,19.777 -36.112,19.767 LED5.A@-35.014,19.767
NetLED5_K: LED5.K Q7.D | length 5.1
  Top Layer w0.127: LED5.K@-33.914,19.767 -33.397,19.25 -31.728,19.25 v2(-31.362,18.884)
  Bottom Layer w0.127: v2@-31.445,18.882 v2@-31.383,18.882 ; v2@-31.4,18.865 v2@-31.383,18.882 ; Q7.D@-30.712,20.712 -30.712,19.553 v2@-31.383,18.882
NetLED6_A: LED6.A R48.1 | length 1.1
  Top Layer w0.254: R48.1@-36.122,18.621 -36.061,18.621 LED6.A@-34.986,18.609
NetLED6_K: LED6.K Q8.D | length 3.7
  Top Layer w0.127: LED6.K@-33.73,18.765 LED6.K@-33.886,18.609 -32.028,18.609 v2(-31.513,18.094)
  Bottom Layer w0.127: v2(-31.513,18.094) -30.742,18.094 Q8.D@-30.661,18.175
NetQ1_D: Q1.D R17.1 SB2.1 | length 2.5
  Top Layer w0.305: SB2.1@-57.118,23.379 -55.843,23.379 R17.1@-55.792,23.43 -55.792,22.347 -55.749,22.304 Q1.D@-55.749,22.299
NetQ5_B: Q5.B R43.2 R45.1 | length 2
  Bottom Layer w0.127: R45.1@-19.1,21.98 R45.1@-19.055,21.936 -19.055,21.664 -18.668,21.276 -18.611,21.276 Q5.B@-18.424,21.09
  Bottom Layer w0.152: R43.2@-19.857,21.98 R45.1@-19.1,21.98
NetQ6_B: Q6.B R44.2 R46.1 | length 1.7
  Top Layer w0.127: Q6.B@-33.072,23.887 -32.378,23.887 R44.2@-32.173,23.682 -32.173,23.019 R46.1@-32.15,22.996
NetR4_2: R4.2 U3.17 | length 1.9
  Bottom Layer w0.152: U3.17@-40.318,19.578 -40.277,19.537 R4.2@-40.277,17.736
NetR5_2: R5.2 U3.16 | length 1.1
  Bottom Layer w0.152: U3.16@-39.568,18.828 -39.568,17.75 R5.2@-39.557,17.739
NetR6_1: R6.1 U3.28 | length 1.8
  Bottom Layer w0.254: R6.1@-38.683,25.385 -38.683,25.063 -38.068,24.448 U3.28@-38.068,23.828
NetR12_1: R12.1 R13.2 | length 0.6
  Top Layer w0.152: R13.2@-31.75,6.461 -31.732,6.443 R12.1@-31.732,5.831
NetR22_1: R22.1 R60.1 U10.2 U10.10 | length 3.5
  Top Layer w0.127: U10.2@-53.848,24.95 -53.165,24.95 -52.765,24.55 U10.10@-52.311,24.55 -51.719,24.55 -51.147,24.55 cw(c-51.147,24.477) -51.074,24.477 -51.074,23.953 cw(c-51.098,23.953) R60.1@-51.098,23.929
NetR30_1: R30.1 R32.1 U8.2 U8.10 | length 3.6
  Top Layer w0.127: R30.1@-48.082,25.187 R30.1@-48.074,25.187 ; R32.1@-48.08,25.646 -48.074,25.646 R30.1@-48.074,25.187 ; U8.10@-45.179,24.55 -45.564,24.55 -45.964,24.95 U8.2@-46.716,24.95 -47.447,24.95 -47.685,25.187 R30.1@-48.074,25.187
NetSB4_1: SB4.1 TP16.1 | length 1.7
  Top Layer w0.584: TP16.1@-5.633,3.834 -5.613,3.854 -5.613,5.506
NetSB17_2: SB17.2 U7.1 | length 3.7
  Top Layer w0.127: U7.1@-21.939,28.135 -21.108,28.135 -19.5,28.135 -19.258,28.377 SB17.2@-18.575,29.06
NetSB18_2: SB18.2 U7.6 | length 1.5
  Top Layer w0.127: SB18.2@-29.072,31.067 -28.68,30.675 U7.6@-27.739,30.675
NetSB19_2: SB19.2 U7.5 | length 1.6
  Top Layer w0.127: SB19.2@-29.047,32.655 -28.337,31.945 U7.5@-27.739,31.945
NetSB20_2: SB20.2 U7.2 | length 1.6
  Top Layer w0.127: U7.2@-21.844,29.5 U7.2@-21.939,29.405 -20.82,29.405 SB20.2@-20.575,29.16
NetSB21_2: SB21.2 U7.3 | length 1.5
  Top Layer w0.127: U7.3@-21.939,30.675 -20.844,30.675 -20.526,30.994
NetSB22_2: SB22.2 U7.7 | length 1.2
  Top Layer w0.127: -28.919,29.447 -27.781,29.447 U7.7@-27.739,29.405
NetTP1_1: TP1.1 U11.39 | length 3.8
  Top Layer w0.127: U11.39@-12.707,17.379 -11.815,17.379 -10.147,15.712 TP1.1@-9.598,15.712
NetTP2_1: TP2.1 U11.38 | length 4.7
  Top Layer w0.127: U11.38@-12.707,16.279 -11.384,16.279 -9.598,14.492 TP2.1@-9.598,13.68
NetTP3_1: TP3.1 U11.5 | length 3.5
  Top Layer w0.127: U11.5@-18.607,25.629 -18.607,26.33 -18.313,26.624 -17.685,26.624 -16.949,27.36 -16.555,27.36 TP3.1@-16.225,27.36
NetTP4_1: TP4.1 U11.6 | length 2.3
  Top Layer w0.127: U11.6@-19.707,25.629 -19.707,26.397 -18.744,27.36 TP4.1@-18.555,27.36
NetTP5_1: TP5.1 U11.100 | length 6.2
  Top Layer w0.127: TP5.1@-31.076,26.401 -31.076,25.132 -30.678,24.734 -29.628,24.734 ; -29.627,24.735 -28.062,24.735 U11.100@-26.807,23.479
